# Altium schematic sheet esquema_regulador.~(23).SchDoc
size A4
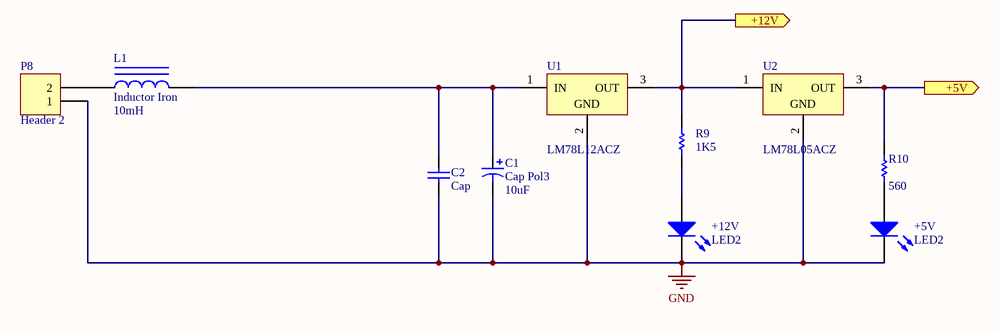
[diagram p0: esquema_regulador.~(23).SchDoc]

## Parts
+5V  LED2  [CAPPR2.5-6.3X5]
+12V  LED2  [CAPPR2.5-6.3X5]
C1  Cap Pol3  value 10uF  [CAPPR3.5-8X15]
C2  Cap  [RAD-0.1]
L1  Inductor Iron  value 10mH  [bobina_Choque]
P8  Header 2  [pwheader1x2]
R9  value 1K5  [AXIAL-0.3]  (hidden comment: Carbon 1/8w 5%)
R10  value 560  [AXIAL-0.3]  (hidden comment: Carbon 1/8w 5%)
U1  LM78L12ACZ  [T03B]
U2  LM78L05ACZ  [T03B]

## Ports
+5V (out), +12V (out)

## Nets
GND: +5V.2(K) +12V.2(K) C1.2 C2.1 P8.1 U1.2(GND) U2.2(GND)
+5V: R10.2 U2.3(OUT) ; port +5V
+12V: R9.2 U1.3(OUT) U2.1(IN) ; port +12V
Net+5V_1: +5V.1(A) R10.1
Net+12V_1: +12V.1(A) R9.1
NetC1_1: C1.1 C2.2 L1.2 U1.1(IN)
NetL1_1: L1.1 P8.2

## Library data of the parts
+5V +12V = LED2: Typical RED, GREEN, YELLOW, AMBER GaAs LED
C1 = Cap Pol3: Polarized Capacitor 35V
C2 = Cap: Capacitor
L1 = Inductor Iron: Magnetic-Core Inductor
P8 = Header 2: Header, 2-Pin
R9 R10 = Res Semi: Semiconductor Resistor
U1 = LM78L12ACZ: 3-Terminal Positive Regulator; PackageDocument: 2000
U2 = LM78L05ACZ: 3-Terminal Positive Regulator; PackageDocument: 2000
